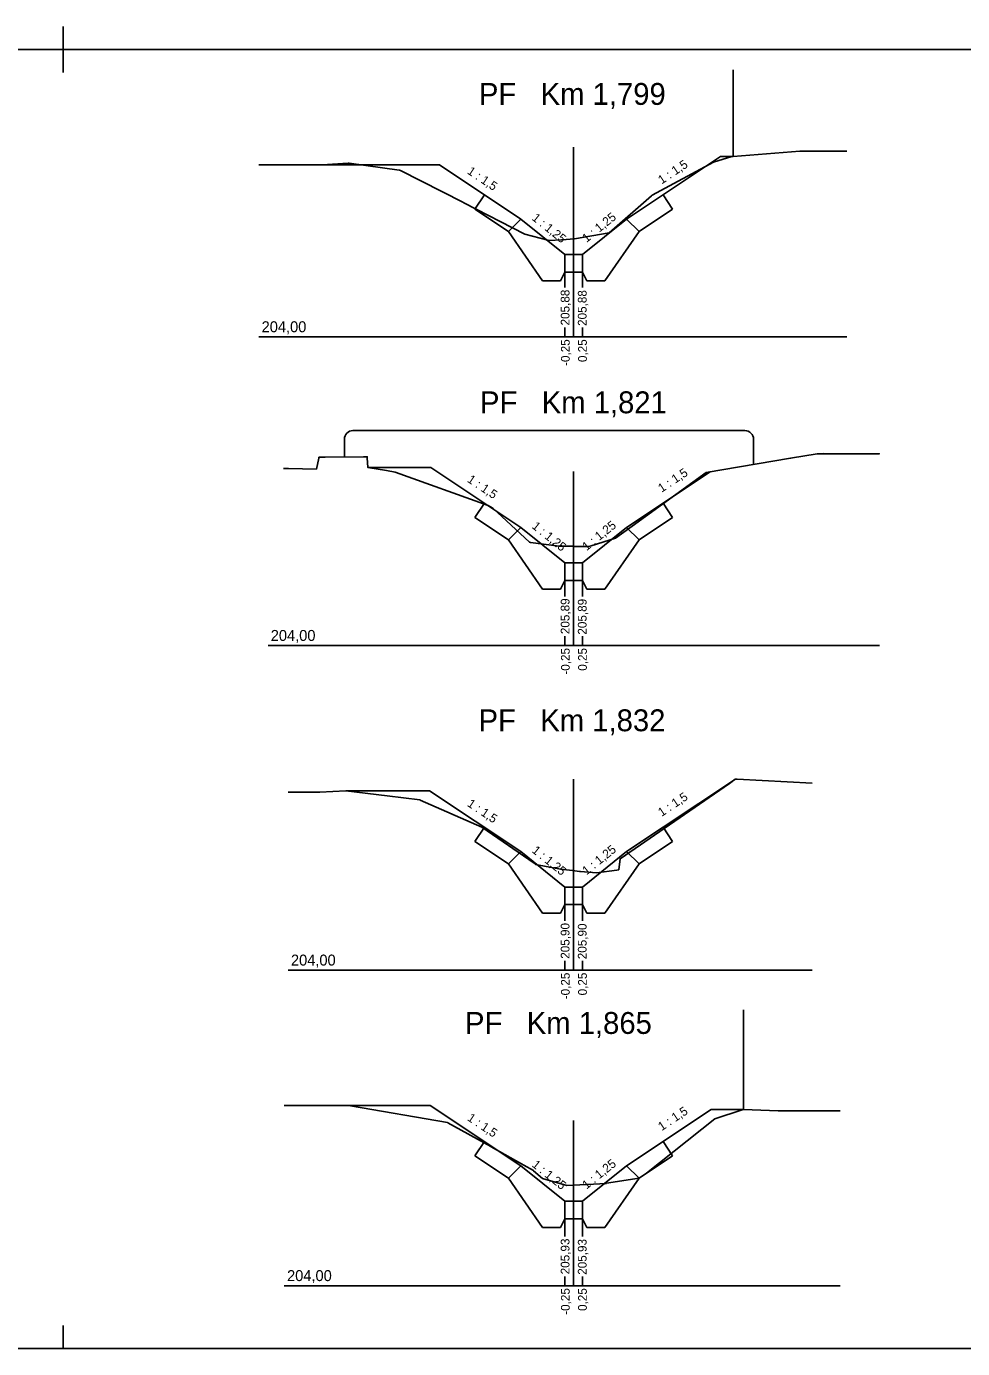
# Model space of a CAD drawing. Extents: x -547174 to -543113, y -1125006 to -1123643.
# Drawn here: x -547111.11 to -547089.7, y -1123837.37 to -1123807.14 of the extents above; entities that cross this region are included whole.
import ezdxf

# ---------------------------------------------------------------- set-up
doc = ezdxf.new("R2010")
doc.units = 0
for name, color, linetype in [('Default', 7, 'Continuous'), ('Profile', 7, 'Continuous'), ('PROFILY NÁVRH', 7, 'Continuous'), ('Section', 7, 'Continuous'), ('STANIČENÍ', 7, 'Continuous')]:
    doc.layers.add(name, color=color, linetype=linetype)

msp = doc.modelspace()

# ---------------------------------------------------------------- linework, layer by layer
at = {"layer": 'Default'}
for points in [[(-547092.351, -1123809.99), (-547093.421, -1123809.99), (-547094.949, -1123810.111), (-547094.967, -1123810.112), (-547094.976, -1123810.115), (-547095.4, -1123810.244), (-547096.8, -1123810.997), (-547096.819, -1123811.011), (-547097.782, -1123811.853), (-547098.577, -1123811.993), (-547098.579, -1123811.994), (-547098.58, -1123811.994), (-547098.869, -1123812.013), (-547098.874, -1123812.013), (-547099.159, -1123812.032), (-547099.185, -1123812.028), (-547099.711, -1123811.884), (-547101.106, -1123811.174), (-547101.134, -1123811.152), (-547102.553, -1123810.434), (-547102.582, -1123810.422), (-547102.586, -1123810.421), (-547103.732, -1123810.263), (-547103.744, -1123810.263), (-547103.752, -1123810.263), (-547104.348, -1123810.303), (-547105.796, -1123810.303)], [(-547092.891, -1123816.904), (-547091.604, -1123816.906), (-547093.023, -1123816.908), (-547093.634, -1123817.011), (-547095.567, -1123817.333), (-547097.259, -1123818.562), (-547097.642, -1123818.839), (-547098.194, -1123819.011), (-547098.255, -1123819.025), (-547098.576, -1123819.025), (-547098.597, -1123819.023), (-547098.908, -1123819.023), (-547098.928, -1123819.021), (-547099.58, -1123818.935), (-547099.607, -1123818.93), (-547100.448, -1123818.152), (-547100.497, -1123818.118), (-547100.554, -1123818.093), (-547102.681, -1123817.326), (-547102.875, -1123817.293), (-547103.307, -1123817.221), (-547103.317, -1123816.998), (-547103.317, -1123816.978), (-547103.4, -1123816.979), (-547104.283, -1123816.987), (-547104.404, -1123816.988), (-547104.424, -1123816.988), (-547104.427, -1123817.011), (-547104.48, -1123817.258), (-547105.117, -1123817.248), (-547105.121, -1123817.248), (-547105.231, -1123817.246)], [(-547093.141, -1123824.44), (-547094.858, -1123824.345), (-547094.884, -1123824.344), (-547094.904, -1123824.351), (-547095.03, -1123824.45), (-547097.529, -1123826.169), (-547097.566, -1123826.419), (-547097.566, -1123826.419), (-547097.61, -1123826.425), (-547098.077, -1123826.491), (-547098.443, -1123826.455), (-547098.451, -1123826.455), (-547098.462, -1123826.455), (-547098.622, -1123826.437), (-547098.83, -1123826.415), (-547098.85, -1123826.412), (-547099.469, -1123826.296), (-547099.497, -1123826.27), (-547100.696, -1123825.448), (-547102.103, -1123824.826), (-547102.109, -1123824.824), (-547102.111, -1123824.823), (-547102.86, -1123824.731), (-547103.804, -1123824.614), (-547103.806, -1123824.614), (-547104.405, -1123824.644), (-547104.419, -1123824.644), (-547105.126, -1123824.644)], [(-547092.499, -1123831.928), (-547093.82, -1123831.928), (-547093.919, -1123831.933), (-547094.715, -1123831.9), (-547094.744, -1123831.909), (-547095.366, -1123832.115), (-547096.932, -1123833.359), (-547097.096, -1123833.469), (-547097.842, -1123833.588), (-547097.847, -1123833.589), (-547098.297, -1123833.612), (-547098.299, -1123833.612), (-547098.301, -1123833.612), (-547098.754, -1123833.638), (-547099.309, -1123833.479), (-547099.31, -1123833.479), (-547099.513, -1123833.299), (-547099.513, -1123833.299), (-547099.513, -1123833.298), (-547099.736, -1123833.173), (-547100.485, -1123832.752), (-547100.49, -1123832.749), (-547100.493, -1123832.747), (-547101.471, -1123832.202), (-547101.478, -1123832.199), (-547103.699, -1123831.813), (-547103.701, -1123831.814), (-547103.704, -1123831.809), (-547104.285, -1123831.809), (-547104.286, -1123831.809), (-547104.287, -1123831.811), (-547105.215, -1123831.811)]]:
    msp.add_lwpolyline(points, dxfattribs=at)
at = {"layer": 'Profile'}
for p, q in [((-547110.272, -1123807.138), (-547110.272, -1123807.666)), ((-547131.272, -1123807.666), (-547110.272, -1123807.666)), ((-547110.272, -1123807.666), (-547091.788, -1123807.666)), ((-547110.272, -1123807.666), (-547089.272, -1123807.666)), ((-547110.272, -1123807.666), (-547110.272, -1123808.194)), ((-547110.272, -1123836.838), (-547110.272, -1123837.366)), ((-547131.272, -1123837.366), (-547110.272, -1123837.366)), ((-547110.272, -1123837.366), (-547089.272, -1123837.366))]:
    msp.add_line(p, q, dxfattribs=at)
at = {"layer": 'PROFILY NÁVRH'}
for p, q in [((-547101.667, -1123810.302), (-547104.348, -1123810.303)), ((-547099.807, -1123811.542), (-547101.667, -1123810.302)), ((-547097.384, -1123811.542), (-547095.238, -1123810.111)), ((-547094.949, -1123810.111), (-547095.238, -1123810.111)), ((-547100.639, -1123810.988), (-547100.857, -1123811.314)), ((-547096.552, -1123810.988), (-547096.334, -1123811.314)), ((-547100.09, -1123811.825), (-547100.857, -1123811.314)), ((-547097.101, -1123811.825), (-547096.334, -1123811.314)), ((-547100.09, -1123811.825), (-547099.807, -1123811.542)), ((-547100.09, -1123811.825), (-547099.311, -1123812.954)), ((-547098.796, -1123812.354), (-547099.807, -1123811.542)), ((-547098.396, -1123812.354), (-547097.384, -1123811.542)), ((-547097.101, -1123811.825), (-547097.88, -1123812.954)), ((-547097.101, -1123811.825), (-547097.384, -1123811.542)), ((-547098.396, -1123812.354), (-547098.796, -1123812.354)), ((-547098.796, -1123812.354), (-547098.796, -1123813.11)), ((-547098.396, -1123812.354), (-547098.396, -1123813.11)), ((-547099.311, -1123812.954), (-547098.896, -1123812.954)), ((-547098.896, -1123812.954), (-547098.796, -1123812.754)), ((-547098.396, -1123812.754), (-547098.796, -1123812.754)), ((-547098.296, -1123812.954), (-547098.396, -1123812.754)), ((-547097.88, -1123812.954), (-547098.296, -1123812.954)), ((-547098.796, -1123814.022), (-547098.796, -1123814.234)), ((-547098.396, -1123814.022), (-547098.396, -1123814.234)), ((-547103.841, -1123816.983), (-547103.841, -1123816.576)), ((-547103.643, -1123816.378), (-547094.68, -1123816.378)), ((-547094.482, -1123816.576), (-547094.482, -1123817.15)), ((-547101.862, -1123817.221), (-547103.307, -1123817.221)), ((-547099.807, -1123818.59), (-547101.862, -1123817.221)), ((-547097.384, -1123818.59), (-547095.475, -1123817.318)), ((-547100.639, -1123818.036), (-547100.857, -1123818.362)), ((-547096.552, -1123818.036), (-547096.334, -1123818.362)), ((-547100.09, -1123818.873), (-547100.857, -1123818.362)), ((-547097.101, -1123818.873), (-547096.334, -1123818.362)), ((-547100.09, -1123818.873), (-547099.807, -1123818.59)), ((-547098.796, -1123819.402), (-547099.807, -1123818.59)), ((-547098.396, -1123819.402), (-547097.384, -1123818.59)), ((-547097.101, -1123818.873), (-547097.384, -1123818.59)), ((-547100.09, -1123818.873), (-547099.311, -1123820.002)), ((-547097.101, -1123818.873), (-547097.88, -1123820.002)), ((-547098.396, -1123819.402), (-547098.796, -1123819.402)), ((-547098.796, -1123819.402), (-547098.796, -1123820.168)), ((-547098.396, -1123819.402), (-547098.396, -1123820.168)), ((-547098.896, -1123820.002), (-547098.796, -1123819.802)), ((-547098.396, -1123819.802), (-547098.796, -1123819.802)), ((-547098.296, -1123820.002), (-547098.396, -1123819.802)), ((-547099.311, -1123820.002), (-547098.896, -1123820.002)), ((-547097.88, -1123820.002), (-547098.296, -1123820.002)), ((-547098.796, -1123821.08), (-547098.796, -1123821.292)), ((-547098.396, -1123821.08), (-547098.396, -1123821.292)), ((-547097.384, -1123826.002), (-547094.897, -1123824.344)), ((-547094.884, -1123824.344), (-547094.897, -1123824.344)), ((-547101.89, -1123824.613), (-547103.804, -1123824.614)), ((-547099.807, -1123826.002), (-547101.89, -1123824.613)), ((-547100.639, -1123825.447), (-547100.857, -1123825.774)), ((-547096.552, -1123825.447), (-547096.334, -1123825.774)), ((-547100.09, -1123826.285), (-547100.857, -1123825.774)), ((-547100.09, -1123826.285), (-547099.807, -1123826.002)), ((-547098.796, -1123826.814), (-547099.807, -1123826.002)), ((-547098.396, -1123826.814), (-547097.384, -1123826.002)), ((-547097.101, -1123826.285), (-547097.384, -1123826.002)), ((-547097.101, -1123826.285), (-547096.334, -1123825.774)), ((-547100.09, -1123826.285), (-547099.311, -1123827.414)), ((-547097.101, -1123826.285), (-547097.88, -1123827.414)), ((-547098.396, -1123826.814), (-547098.796, -1123826.814)), ((-547098.796, -1123826.814), (-547098.796, -1123827.59)), ((-547098.396, -1123826.814), (-547098.396, -1123827.59)), ((-547098.896, -1123827.414), (-547098.796, -1123827.214)), ((-547098.396, -1123827.214), (-547098.796, -1123827.214)), ((-547098.296, -1123827.414), (-547098.396, -1123827.214)), ((-547099.311, -1123827.414), (-547098.896, -1123827.414)), ((-547097.88, -1123827.414), (-547098.296, -1123827.414)), ((-547098.796, -1123828.502), (-547098.796, -1123828.714)), ((-547098.396, -1123828.502), (-547098.396, -1123828.714)), ((-547101.875, -1123831.808), (-547103.704, -1123831.809)), ((-547099.807, -1123833.187), (-547101.875, -1123831.808)), ((-547097.384, -1123833.187), (-547095.453, -1123831.9)), ((-547094.715, -1123831.9), (-547095.453, -1123831.9)), ((-547100.639, -1123832.632), (-547100.857, -1123832.958)), ((-547096.552, -1123832.632), (-547096.334, -1123832.958)), ((-547100.09, -1123833.47), (-547100.857, -1123832.958)), ((-547097.101, -1123833.47), (-547096.334, -1123832.958)), ((-547100.09, -1123833.47), (-547099.807, -1123833.187)), ((-547098.796, -1123833.999), (-547099.807, -1123833.187)), ((-547098.396, -1123833.999), (-547097.384, -1123833.187)), ((-547097.101, -1123833.47), (-547097.384, -1123833.187)), ((-547100.09, -1123833.47), (-547099.311, -1123834.599)), ((-547097.101, -1123833.47), (-547097.88, -1123834.599)), ((-547098.396, -1123833.999), (-547098.796, -1123833.999)), ((-547098.796, -1123833.999), (-547098.796, -1123834.804)), ((-547098.396, -1123833.999), (-547098.396, -1123834.804)), ((-547098.896, -1123834.599), (-547098.796, -1123834.399)), ((-547098.396, -1123834.399), (-547098.796, -1123834.399)), ((-547098.296, -1123834.599), (-547098.396, -1123834.399)), ((-547099.311, -1123834.599), (-547098.896, -1123834.599)), ((-547097.88, -1123834.599), (-547098.296, -1123834.599)), ((-547098.796, -1123835.716), (-547098.796, -1123835.929)), ((-547098.396, -1123835.716), (-547098.396, -1123835.929))]:
    msp.add_line(p, q, dxfattribs=at)
for centre, start, end in [((-547103.643, -1123816.576), 90, 180), ((-547094.68, -1123816.576), 0, 90)]:
    msp.add_arc(centre, 0.198, start, end, dxfattribs=at)
at = {"layer": 'Section'}
for p, q in [((-547098.596, -1123809.898), (-547098.596, -1123814.234)), ((-547105.796, -1123814.234), (-547092.351, -1123814.234)), ((-547098.596, -1123817.316), (-547098.596, -1123821.292)), ((-547105.587, -1123821.292), (-547091.604, -1123821.292)), ((-547098.596, -1123824.346), (-547098.596, -1123828.714)), ((-547105.126, -1123828.714), (-547093.141, -1123828.714)), ((-547098.596, -1123832.15), (-547098.596, -1123835.929)), ((-547105.215, -1123835.929), (-547092.499, -1123835.929))]:
    msp.add_line(p, q, dxfattribs=at)
at = {"layer": 'STANIČENÍ'}
for p, q in [((-547094.949, -1123810.111), (-547094.949, -1123808.129)), ((-547094.715, -1123831.9), (-547094.715, -1123829.624))]:
    msp.add_line(p, q, dxfattribs=at)

# ---------------------------------------------------------------- texts
at = {"layer": 'PROFILY NÁVRH'}
for s, rotation, p in [('1 : 1,5', 33.6901, (-547096.583, -1123810.752)), ('1 : 1,5', 326.3099, (-547101.046, -1123810.491)), ('1 : 1,25', 321.2587, (-547099.566, -1123811.546)), ('1 : 1,25', 38.7413, (-547098.301, -1123812.088)), ('205,88', 90, (-547098.692, -1123813.974)), ('205,88', 90, (-547098.3, -1123813.985)), ('-0,25', 90, (-547098.686, -1123814.9)), ('0,25', 90, (-547098.295, -1123814.811)), ('1 : 1,5', 33.6901, (-547096.583, -1123817.801)), ('1 : 1,5', 326.3099, (-547101.046, -1123817.539)), ('1 : 1,25', 38.7413, (-547098.301, -1123819.136)), ('1 : 1,25', 321.2587, (-547099.566, -1123818.594)), ('205,89', 90, (-547098.692, -1123821.032)), ('205,89', 90, (-547098.3, -1123821.043)), ('-0,25', 90, (-547098.686, -1123821.958)), ('0,25', 90, (-547098.295, -1123821.869)), ('1 : 1,5', 326.3099, (-547101.046, -1123824.951)), ('1 : 1,5', 33.6901, (-547096.583, -1123825.212)), ('1 : 1,25', 321.2587, (-547099.566, -1123826.006)), ('1 : 1,25', 38.7413, (-547098.301, -1123826.548)), ('205,90', 90, (-547098.692, -1123828.454)), ('205,90', 90, (-547098.3, -1123828.465)), ('-0,25', 90, (-547098.686, -1123829.38)), ('0,25', 90, (-547098.295, -1123829.291)), ('1 : 1,5', 326.3099, (-547101.046, -1123832.136)), ('1 : 1,5', 33.6901, (-547096.583, -1123832.397)), ('1 : 1,25', 321.2587, (-547099.566, -1123833.191)), ('1 : 1,25', 38.7413, (-547098.301, -1123833.732)), ('205,93', 90, (-547098.692, -1123835.669)), ('205,93', 90, (-547098.3, -1123835.679)), ('-0,25', 90, (-547098.686, -1123836.594)), ('0,25', 90, (-547098.295, -1123836.506))]:
    msp.add_text(s, height=0.2, rotation=rotation, dxfattribs=at).set_placement(p)
at = {"layer": 'Section'}
for s, height, p in [('PF   Km 1,799', 0.5, (-547100.763, -1123808.931)), ('204,00', 0.25, (-547105.733, -1123814.129)), ('PF   Km 1,821', 0.5, (-547100.738, -1123815.982)), ('204,00', 0.25, (-547105.524, -1123821.187)), ('PF   Km 1,832', 0.5, (-547100.771, -1123823.252)), ('204,00', 0.25, (-547105.062, -1123828.609)), ('PF   Km 1,865', 0.5, (-547101.081, -1123830.172)), ('204,00', 0.25, (-547105.151, -1123835.823))]:
    msp.add_text(s, height=height, dxfattribs=at).set_placement(p)

doc.saveas('drawing.dxf')
